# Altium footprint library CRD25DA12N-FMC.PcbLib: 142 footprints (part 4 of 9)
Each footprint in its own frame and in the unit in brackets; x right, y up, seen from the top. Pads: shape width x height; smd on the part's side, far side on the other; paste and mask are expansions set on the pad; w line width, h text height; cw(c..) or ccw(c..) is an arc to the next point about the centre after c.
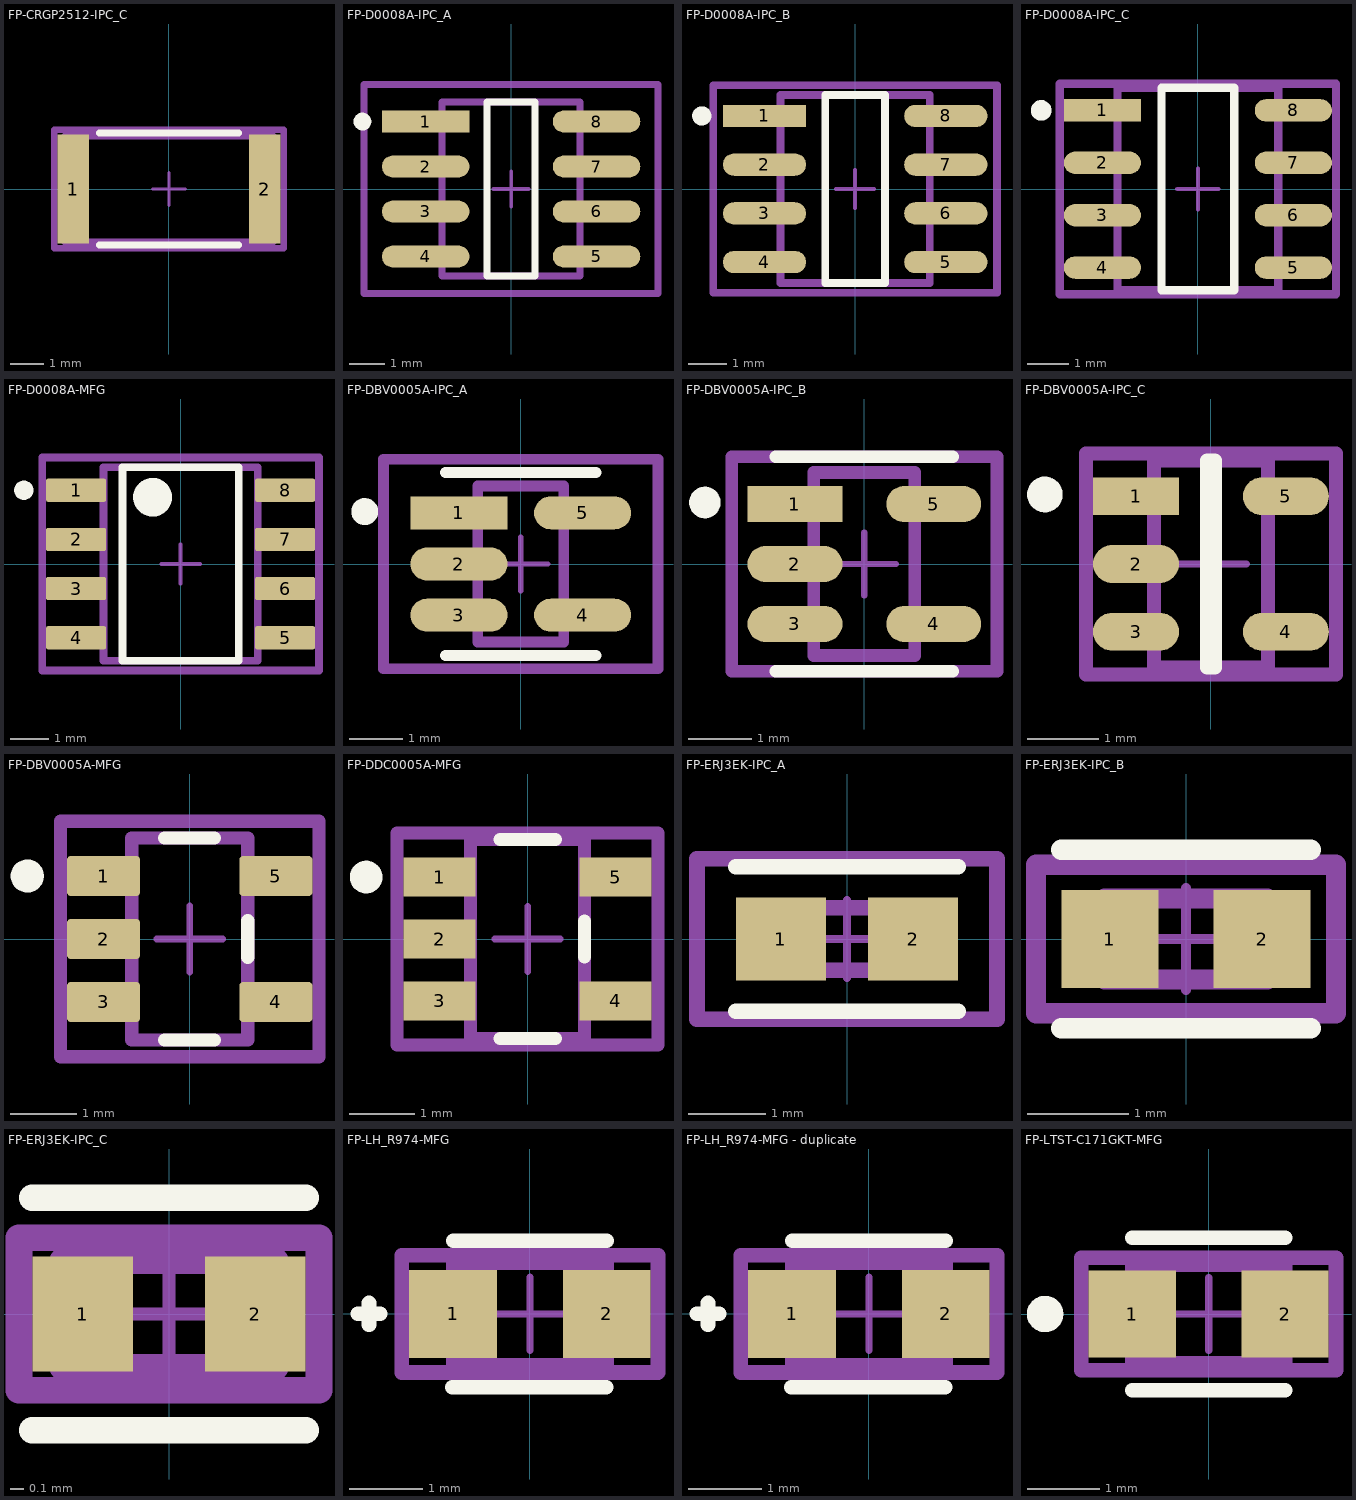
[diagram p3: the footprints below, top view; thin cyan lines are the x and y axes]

## FP-CRGP2512-IPC_C [mm]
pads (2):
  rect 0.958x3.306 smd paste+0 mask+0: 1(-2.902,0) 2(2.902,0)
Top Overlay:
  lines w0.2: -2.123,-1.7 2.123,-1.7 ; -2.123,1.7 2.123,1.7
Mechanical 5:
  lines w0.2: -3.481,-1.8 -3.481,1.8 3.481,1.8 3.481,-1.8 -3.481,-1.8
  text ".Designator" at 0,0.188 h1
Mechanical 13:
  lines w0.2: -3.175,-1.6 -3.175,1.6 3.175,1.6 3.175,-1.6 -3.175,-1.6
Mechanical 15:
  lines w0.2: -3.481,-1.8 -3.481,1.8 3.481,1.8 3.481,-1.8 -3.481,-1.8
Mechanical 16:
  lines w0.1: -0.5,0 0.5,0 ; 0,-0.5 0,0.5
3D body "Res_TE_CRGP2512F47R_eec.STEP": height 0.25, standoff 0, extent -3.481,-1.8 3.481,1.8

## FP-D0008A-IPC_A [mm]
pads (8):
  rect 2.469x0.622 smd paste+0 mask+0: 1(-2.414,1.905)
  rrect100% 2.469x0.622 smd paste+0 mask+0: 2(-2.414,0.635) 3(-2.414,-0.635) 4(-2.414,-1.905) 5(2.414,-1.905) 6(2.414,-0.635) 7(2.414,0.635) 8(2.414,1.905)
Top Overlay:
  circle w0.25: c-4.198,1.905 r0.125
  lines w0.2: -0.679,-2.452 0.679,-2.452 0.679,2.452 -0.679,2.452 -0.679,-2.452
Mechanical 5:
  lines w0.2: -4.148,-2.953 4.148,-2.953 4.148,2.953 -4.148,2.953 -4.148,-2.953
  text ".Designator" at 0,0.188 h1
Mechanical 13:
  lines w0.2: -1.947,-2.452 1.947,-2.452 1.947,2.452 -1.947,2.452 -1.947,-2.452
Mechanical 15:
  lines w0.2: -4.148,-2.953 4.148,-2.953 4.148,2.953 -4.148,2.953 -4.148,-2.953
Mechanical 16:
  lines w0.1: -0.5,0 0.5,0 ; 0,-0.5 0,0.5
3D body "IC_Texas_Instruments_ISO7220ADR_eec.STEP": height 0.25, standoff 0, extent -4.148,-2.953 4.148,2.953

## FP-D0008A-IPC_B [mm]
pads (8):
  rect 2.169x0.582 smd paste+0 mask+0: 1(-2.364,1.905)
  rrect100% 2.169x0.582 smd paste+0 mask+0: 2(-2.364,0.635) 3(-2.364,-0.635) 4(-2.364,-1.905) 5(2.364,-1.905) 6(2.364,-0.635) 7(2.364,0.635) 8(2.364,1.905)
Top Overlay:
  circle w0.25: c-3.998,1.905 r0.125
  lines w0.2: -0.779,-2.452 -0.779,2.452 0.779,2.452 0.779,-2.452 -0.779,-2.452
Mechanical 5:
  lines w0.2: -3.698,-2.702 -3.698,2.702 3.698,2.702 3.698,-2.702 -3.698,-2.702
  text ".Designator" at 0,0.188 h1
Mechanical 13:
  lines w0.2: -1.947,-2.452 -1.947,2.452 1.947,2.452 1.947,-2.452 -1.947,-2.452
Mechanical 15:
  lines w0.2: -3.698,-2.702 -3.698,2.702 3.698,2.702 3.698,-2.702 -3.698,-2.702
Mechanical 16:
  lines w0.1: -0.5,0 0.5,0 ; 0,-0.5 0,0.5
3D body "IC_Texas_Instruments_ISO7220ADR_eec.STEP": height 0.25, standoff 0, extent -3.698,-2.702 3.698,2.702

## FP-D0008A-IPC_C [mm]
pads (8):
  rect 1.869x0.542 smd paste+0 mask+0: 1(-2.314,1.905)
  rrect100% 1.869x0.542 smd paste+0 mask+0: 2(-2.314,0.635) 3(-2.314,-0.635) 4(-2.314,-1.905) 5(2.314,-1.905) 6(2.314,-0.635) 7(2.314,0.635) 8(2.314,1.905)
Top Overlay:
  circle w0.25: c-3.798,1.905 r0.125
  lines w0.2: -0.879,-2.452 -0.879,2.452 0.879,2.452 0.879,-2.452 -0.879,-2.452
Mechanical 5:
  lines w0.2: -3.348,-2.552 -3.348,2.552 3.348,2.552 3.348,-2.552 -3.348,-2.552
  text ".Designator" at 0,0.188 h1
Mechanical 13:
  lines w0.2: -1.947,-2.452 -1.947,2.452 1.947,2.452 1.947,-2.452 -1.947,-2.452
Mechanical 15:
  lines w0.2: -3.348,-2.552 -3.348,2.552 3.348,2.552 3.348,-2.552 -3.348,-2.552
Mechanical 16:
  lines w0.1: -0.5,0 0.5,0 ; 0,-0.5 0,0.5
3D body "IC_Texas_Instruments_ISO7220ADR_eec.STEP": height 0.25, standoff 0, extent -3.348,-2.552 3.348,2.552

## FP-D0008A-MFG [mm]
pads (8):
  rrect17% 1.55x0.6 smd paste+0 mask+0: 1(-2.7,1.905) 2(-2.7,0.635) 3(-2.7,-0.635) 4(-2.7,-1.905) 5(2.7,-1.905) 6(2.7,-0.635) 7(2.7,0.635) 8(2.7,1.905)
Top Overlay:
  circle w0.5: c-0.725,1.725 r0.25
  circle w0.25: c-4.05,1.905 r0.125
  lines w0.2: -1.5,-2.5 -1.5,2.5 1.5,2.5 1.5,-2.5 -1.5,-2.5
Mechanical 5:
  lines w0.2: -3.575,-2.75 -3.575,2.75 3.575,2.75 3.575,-2.75 -3.575,-2.75
  text ".Designator" at 0,0.188 h1
Mechanical 13:
  lines w0.2: -1.99,-2.5 -1.99,2.5 1.99,2.5 1.99,-2.5 -1.99,-2.5
Mechanical 15:
  lines w0.2: -3.575,-2.75 -3.575,2.75 3.575,2.75 3.575,-2.75 -3.575,-2.75
Mechanical 16:
  lines w0.1: -0.5,0 0.5,0 ; 0,-0.5 0,0.5
3D body "IC_Texas_Instruments_ISO7220ADR_eec.STEP": height 0.25, standoff 0, extent -3.575,-2.75 3.575,2.75

## FP-DBV0005A-IPC_A [mm]
pads (5):
  rect 1.805x0.612 smd paste+0 mask+0: 1(-1.15,0.95)
  rrect100% 1.805x0.612 smd paste+0 mask+0: 2(-1.15,0) 3(-1.15,-0.95) 4(1.15,-0.95) 5(1.15,0.95)
Top Overlay:
  circle w0.25: c-2.903,0.975 r0.125
  lines w0.2: -1.4,-1.7 1.4,-1.7 ; -1.4,1.7 1.4,1.7
Mechanical 5:
  lines w0.2: -2.553,-1.95 -2.553,1.95 2.553,1.95 2.553,-1.95 -2.553,-1.95
  text ".Designator" at 0,0 h1
Mechanical 13:
  lines w0.2: -0.8,-1.45 -0.8,1.45 0.8,1.45 0.8,-1.45 -0.8,-1.45
Mechanical 15:
  lines w0.2: -2.553,-1.95 -2.553,1.95 2.553,1.95 2.553,-1.95 -2.553,-1.95
Mechanical 16:
  lines w0.1: -0.5,0 0.5,0 ; 0,-0.5 0,0.5
3D body "IC_Texas_Instruments_SN74AHC1G00DBVR_eec.STEP": height 0.25, standoff 0, extent -2.553,-1.95 2.553,1.95

## FP-DBV0005A-IPC_B [mm]
pads (5):
  rect 1.505x0.572 smd paste+0 mask+0: 1(-1.1,0.95)
  rrect100% 1.505x0.572 smd paste+0 mask+0: 2(-1.1,0) 3(-1.1,-0.95) 4(1.1,-0.95) 5(1.1,0.95)
Top Overlay:
  circle w0.25: c-2.528,0.975 r0.125
  lines w0.2: -1.4,-1.7 1.4,-1.7 ; -1.4,1.7 1.4,1.7
Mechanical 5:
  lines w0.2: -2.103,-1.7 2.103,-1.7 2.103,1.7 -2.103,1.7 -2.103,-1.7
  text ".Designator" at 0,0 h1
Mechanical 13:
  lines w0.2: -0.8,-1.45 0.8,-1.45 0.8,1.45 -0.8,1.45 -0.8,-1.45
Mechanical 15:
  lines w0.2: -2.103,-1.7 2.103,-1.7 2.103,1.7 -2.103,1.7 -2.103,-1.7
Mechanical 16:
  lines w0.1: -0.5,0 0.5,0 ; 0,-0.5 0,0.5
3D body "IC_Texas_Instruments_SN74AHC1G00DBVR_eec.STEP": height 0.25, standoff 0, extent -2.103,-1.7 2.103,1.7

## FP-DBV0005A-IPC_C [mm]
pads (5):
  rect 1.205x0.532 smd paste+0 mask+0: 1(-1.05,0.95)
  rrect100% 1.205x0.532 smd paste+0 mask+0: 2(-1.05,0) 3(-1.05,-0.95) 4(1.05,-0.95) 5(1.05,0.95)
Top Overlay:
  circle w0.25: c-2.328,0.975 r0.125
  lines w0.2: -0.052,-1.45 -0.052,1.45 0.052,1.45 0.052,-1.45 -0.052,-1.45
Mechanical 5:
  lines w0.2: -1.753,-1.55 1.753,-1.55 1.753,1.55 -1.753,1.55 -1.753,-1.55
  text ".Designator" at 0,0.188 h1
Mechanical 13:
  lines w0.2: -0.8,-1.45 0.8,-1.45 0.8,1.45 -0.8,1.45 -0.8,-1.45
Mechanical 15:
  lines w0.2: -1.753,-1.55 1.753,-1.55 1.753,1.55 -1.753,1.55 -1.753,-1.55
Mechanical 16:
  lines w0.1: -0.5,0 0.5,0 ; 0,-0.5 0,0.5
3D body "IC_Texas_Instruments_SN74AHC1G00DBVR_eec.STEP": height 0.25, standoff 0, extent -1.753,-1.55 1.753,1.55

## FP-DBV0005A-MFG [mm]
pads (5):
  rrect17% 1.1x0.6 smd paste+0 mask+0: 1(-1.3,0.95) 2(-1.3,0) 3(-1.3,-0.95) 4(1.3,-0.95) 5(1.3,0.95)
Top Overlay:
  circle w0.25: c-2.45,0.95 r0.125
  lines w0.2: -0.375,-1.525 0.375,-1.525 ; -0.375,1.525 0.375,1.525 ; 0.875,-0.275 0.875,0.275
Mechanical 5:
  lines w0.2: -1.95,-1.775 1.95,-1.775 1.95,1.775 -1.95,1.775 -1.95,-1.775
  text ".Designator" at 0,0 h1
Mechanical 13:
  lines w0.2: -0.875,-1.525 0.875,-1.525 0.875,1.525 -0.875,1.525 -0.875,-1.525
Mechanical 15:
  lines w0.2: -1.95,-1.775 1.95,-1.775 1.95,1.775 -1.95,1.775 -1.95,-1.775
Mechanical 16:
  lines w0.1: -0.5,0 0.5,0 ; 0,-0.5 0,0.5
3D body "IC_Texas_Instruments_SN65LVDT2DBVT_eec.STEP": height 0.25, standoff 0, extent -1.95,-1.775 1.95,1.775

## FP-DDC0005A-MFG [mm]
pads (5):
  rect 1.1x0.6 smd paste+0 mask+0: 1(-1.35,0.95) 2(-1.35,0) 3(-1.35,-0.95) 4(1.35,-0.95) 5(1.35,0.95)
Top Overlay:
  circle w0.25: c-2.475,0.95 r0.125
  lines w0.2: -0.425,-1.525 0.425,-1.525 ; -0.425,1.525 0.425,1.525 ; 0.875,-0.275 0.875,0.275
Mechanical 5:
  lines w0.2: -2,-1.625 -2,1.625 2,1.625 2,-1.625 -2,-1.625
  text ".Designator" at 0,0 h1
Mechanical 13:
  lines w0.2: -0.875,-1.525 -0.875,1.525 0.875,1.525 0.875,-1.525 -0.875,-1.525
Mechanical 15:
  lines w0.2: -2,-1.625 -2,1.625 2,1.625 2,-1.625 -2,-1.625
Mechanical 16:
  lines w0.1: -0.5,0 0.5,0 ; 0,-0.5 0,0.5
3D body "IC_Texas_Instruments_TPS62561DDCT_eec.STEP": height 0.25, standoff 0, extent -2,-1.625 2,1.625

## FP-ERJ3EK-IPC_A [mil]
pads (2):
  rect 45.53x41.82 smd paste+0 mask+0: 1(-33.5,0) 2(33.5,0)
Top Overlay:
  lines w7.87: -56.26,-36.66 56.26,-36.66 ; -56.26,36.66 56.26,36.66
Mechanical 5:
  lines w7.87: -75.95,-40.59 75.95,-40.59 75.95,40.59 -75.95,40.59 -75.95,-40.59
  text ".Designator" at 0,7.4 h39.37
Mechanical 13:
  lines w7.87: -31.5,-15.75 31.5,-15.75 31.5,15.75 -31.5,15.75 -31.5,-15.75
Mechanical 15:
  lines w7.87: -75.95,-40.59 75.95,-40.59 75.95,40.59 -75.95,40.59 -75.95,-40.59
Mechanical 16:
  lines w3.94: -19.68,0 19.68,0 ; 0,-19.68 0,19.68
3D body "Res_Panasonic_ERJ-3EKF12R0V_eec.STEP": height 10, standoff 0, extent -75.95,-40.59 75.95,40.59

## FP-ERJ3EK-IPC_B [mm]
pads (2):
  rect 0.957x0.962 smd paste+0 mask+0: 1(-0.751,0) 2(0.751,0)
Top Overlay:
  lines w0.2: -1.229,-0.881 1.229,-0.881 ; -1.229,0.881 1.229,0.881
Mechanical 5:
  lines w0.2: -1.479,-0.731 1.479,-0.731 1.479,0.731 -1.479,0.731 -1.479,-0.731
  text ".Designator" at 0,0.188 h1
Mechanical 13:
  lines w0.2: -0.8,-0.4 0.8,-0.4 0.8,0.4 -0.8,0.4 -0.8,-0.4
Mechanical 15:
  lines w0.2: -1.479,-0.731 1.479,-0.731 1.479,0.731 -1.479,0.731 -1.479,-0.731
Mechanical 16:
  lines w0.1: -0.5,0 0.5,0 ; 0,-0.5 0,0.5
3D body "Res_Panasonic_ERJ-3EKF12R0V_eec.STEP": height 0.25, standoff 0, extent -1.479,-0.731 1.479,0.731

## FP-ERJ3EK-IPC_C [mm]
pads (2):
  rect 0.757x0.862 smd paste+0 mask+0: 1(-0.651,0) 2(0.651,0)
Top Overlay:
  lines w0.2: -1.029,-0.875 1.029,-0.875 ; -1.029,0.875 1.029,0.875
Mechanical 5:
  lines w0.2: -1.129,-0.575 1.129,-0.575 1.129,0.575 -1.129,0.575 -1.129,-0.575
  text ".Designator" at 0,0.188 h1
Mechanical 13:
  lines w0.2: -0.8,-0.4 0.8,-0.4 0.8,0.4 -0.8,0.4 -0.8,-0.4
Mechanical 15:
  lines w0.2: -1.129,-0.575 1.129,-0.575 1.129,0.575 -1.129,0.575 -1.129,-0.575
Mechanical 16:
  lines w0.1: -0.5,0 0.5,0 ; 0,-0.5 0,0.5
3D body "Res_Panasonic_ERJ-3EKF12R0V_eec.STEP": height 0.25, standoff 0, extent -1.129,-0.575 1.129,0.575

## FP-LH_R974-MFG [mm]
pads (2):
  rect 1.2x1.2 smd paste+0 mask+0: 1(-1.05,0) 2(1.05,0)
Top Overlay:
  lines w0.2: -2.35,0 -2.05,0 ; -2.2,-0.15 -2.2,0.15 ; -1.061,-1.002 1.039,-1.002 ; -1.05,1 1.05,1
Mechanical 5:
  lines w0.2: -1.75,-0.8 1.75,-0.8 1.75,0.8 -1.75,0.8 -1.75,-0.8
  text ".Designator" at 0,0 h1
Mechanical 13:
  lines w0.2: -1.05,-0.7 1.05,-0.7 1.05,0.7 -1.05,0.7 -1.05,-0.7
Mechanical 15:
  lines w0.2: -1.75,-0.8 1.75,-0.8 1.75,0.8 -1.75,0.8 -1.75,-0.8
Mechanical 16:
  lines w0.1: -0.5,0 0.5,0 ; 0,-0.5 0,0.5
3D body "Diode_OSRAM_LH_R974-LP-1_eec.STEP": height 0.25, standoff 0, extent -1.75,-0.8 1.75,0.8

## FP-LH_R974-MFG - duplicate [mm]
pads (2):
  rect 1.2x1.2 smd paste+0 mask+0: 1(-1.05,0) 2(1.05,0)
Top Overlay:
  lines w0.2: -2.35,0 -2.05,0 ; -2.2,-0.15 -2.2,0.15 ; -1.061,-1.002 1.039,-1.002 ; -1.05,1 1.05,1
Mechanical 5:
  lines w0.2: -1.75,-0.8 1.75,-0.8 1.75,0.8 -1.75,0.8 -1.75,-0.8
  text ".Designator" at 0,0 h1
Mechanical 13:
  lines w0.2: -1.05,-0.7 1.05,-0.7 1.05,0.7 -1.05,0.7 -1.05,-0.7
Mechanical 15:
  lines w0.2: -1.75,-0.8 1.75,-0.8 1.75,0.8 -1.75,0.8 -1.75,-0.8
Mechanical 16:
  lines w0.1: -0.5,0 0.5,0 ; 0,-0.5 0,0.5
3D body "Diode_OSRAM_LH_R974-LP-1_eec.STEP": height 0.25, standoff 0, extent -1.75,-0.8 1.75,0.8

## FP-LTST-C171GKT-MFG [mm]
pads (2):
  rect 1.2x1.2 smd paste+0 mask+0: 1(-1.05,0) 2(1.05,0)
Top Overlay:
  circle w0.25: c-2.25,0 r0.125
  lines w0.2: -1.05,-1.05 1.05,-1.05 ; -1.05,1.05 1.05,1.05
Mechanical 5:
  lines w0.2: -1.75,-0.775 -1.75,0.775 1.75,0.775 1.75,-0.775 -1.75,-0.775
  text ".Designator" at 0,0 h1
Mechanical 13:
  lines w0.2: -1.05,-0.675 -1.05,0.675 1.05,0.675 1.05,-0.675 -1.05,-0.675
Mechanical 15:
  lines w0.2: -1.75,-0.775 -1.75,0.775 1.75,0.775 1.75,-0.775 -1.75,-0.775
Mechanical 16:
  lines w0.1: -0.5,0 0.5,0 ; 0,-0.5 0,0.5
3D body "Diode_Lite-On_LTST-C171GKT_eec.STEP": height 0.25, standoff 0, extent -1.75,-0.775 1.75,0.775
